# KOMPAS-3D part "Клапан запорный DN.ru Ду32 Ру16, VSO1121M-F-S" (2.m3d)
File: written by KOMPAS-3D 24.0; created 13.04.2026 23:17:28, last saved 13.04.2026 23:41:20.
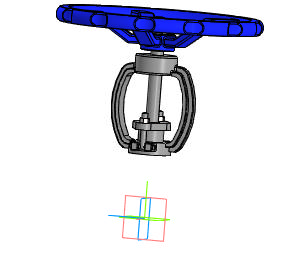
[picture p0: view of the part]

Document properties: Автор: R2D2; Полное имя файла: E:\Работа\Зайцев\VSO3131M-F-S Клапан запорный DN.ru Ду15-100 Ру40\DN32\исходные материалы\2.m3d

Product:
- Component [detail]: Деталь1  | qty 1  | pos. 1  | Автор: R2D2; additional columns: Типовые; source file: VSO1121M-F-S>Деталь (локальная) 1 1.m3d
- Component [detail]: Деталь2  | qty 1  | pos. 2  | Масса: 2.490435; Автор: R2D2; additional columns: Типовые; source file: VSO1121M-F-S>Деталь (локальная) 2 1.m3d
- Component [detail]: ANSI B18.2.4.2M - M14x2 - 21  | designation ANSI B18.2.4.2M - M14x2  | qty 1  | pos. 3  | Масса: 0.029972; Комментарий: Типы метрических   шестигранных гаек   2; Автор: R2D2; additional columns: Сталь, мягкая; source file: VSO1121M-F-S>Деталь (локальная) 3 1.m3d
- Component [detail]: ANSI B18.2.4.2M - M6x1 - 10  | designation ANSI B18.2.4.2M - M6x1  | qty 1  | pos. 4  | Масса: 0.003008; Комментарий: Типы метрических   шестигранных гаек   2; Автор: R2D2; additional columns: Сталь, мягкая; source file: VSO1121M-F-S>Деталь (локальная) 4 1.m3d
- Component [detail]: ANSI B18.2.4.2M - M6x1 - 10  | designation ANSI B18.2.4.2M - M6x1  | qty 1  | pos. 4  | Масса: 0.003008; Комментарий: Типы метрических   шестигранных гаек   2; Автор: R2D2; additional columns: Сталь, мягкая; source file: VSO1121M-F-S>Деталь (локальная) 5 1.m3d
- Part/product: Клапан запорный DN.ru Ду32 Ру16  | designation VSO1121M-F-S
    Масса: 7.9
    Раздел спецификации: Прочие изделия
    Примечание: D090-01945

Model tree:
1. Эскиз:1  (labels: Ребро.Твердое тело1)
2. Элемент выдавливания:1
     Расстояние 1 = 500
3. Эскиз:2  (with: Ребро.Элемент выдавливания:1)  (labels: Ребро.Твердое тело1)
4. Элемент вращения:1
     Угол 1 = 360
5. Эскиз:3  (labels: Вершина.Твердое тело1; Ребро.Твердое тело1)
6. Элемент выдавливания:2
     Расстояние 2 = 10
7. Элемент выдавливания:3  (labels: Грань.Твердое тело1; Твердое тело1; Solid1)
     Расстояние 1 = 30

Referenced files: VSO1121M-F-S>Деталь (локальная) 1 1.m3d, VSO1121M-F-S>Деталь (локальная) 2 1.m3d, VSO1121M-F-S>Деталь (локальная) 3 1.m3d, VSO1121M-F-S>Деталь (локальная) 4 1.m3d, VSO1121M-F-S>Деталь (локальная) 5 1.m3d
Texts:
  VSO1121M-F-S
  Деталь1 Деталь1
  Деталь2 Деталь2
  ANSI B18.2.4.2M - M14x2 ANSI B18.2.4.2M - M14x2 - 21
  ANSI B18.2.4.2M - M6x1 ANSI B18.2.4.2M - M6x1 - 10
  Ось Z.Начало координат
  Ось Y.Начало координат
